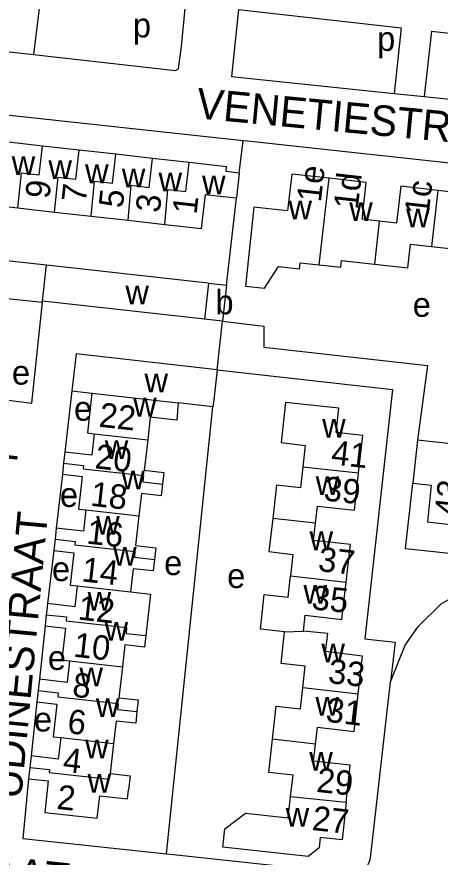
# Model space of a CAD drawing. Extents: x 161936 to 163647, y 386450 to 388633.
# Drawn here: x 162845.1 to 162914.6, y 388209.6 to 388347.4 of the extents above; entities that cross this region are included whole.
import ezdxf

# ---------------------------------------------------------------- set-up
doc = ezdxf.new("R2010")
doc.units = 0
for name, color, linetype in [('BLT_Basislijn', 7, 'Continuous'), ('BLT_Bebouwing', 7, 'Continuous'), ('BLT_Centroide', 7, 'Continuous'), ('BLT_Huisnummer', 7, 'Continuous'), ('BLT_Huisnummer_ tussenligend', 7, 'Continuous'), ('BLT_Onderverdeling_panden', 7, 'Continuous'), ('BLT_Straatnaam', 7, 'Continuous')]:
    doc.layers.add(name, color=color, linetype=linetype)

msp = doc.modelspace()

# ---------------------------------------------------------------- linework, layer by layer
at = {"layer": 'BLT_Basislijn'}
for p, q in [((162849.18, 388352.56), (162847.79, 388341.21)), ((162872.08, 388342.54), (162872.83, 388349.94)), ((162881.44, 388348.58), (162880.32, 388337.62)), ((162908.19, 388345.61), (162907, 388334.84)), ((162913.16, 388345.06), (162911.97, 388334.32)), ((162842.82, 388341.76), (162847.79, 388341.21)), ((162880.32, 388337.62), (162907, 388334.84)), ((162882.23, 388327.06), (162798.44, 388336.12)), ((162907, 388334.84), (162911.97, 388334.32)), ((162911.97, 388334.32), (162937.75, 388331.64)), ((162881.58, 388321.77), (162882.23, 388327.06)), ((162879.49, 388303.39), (162881.11, 388317.7)), ((162849.92, 388306.66), (162795.81, 388312.41)), ((162841.69, 388301.4), (162849.25, 388300.61)), ((162849.25, 388300.61), (162849.27, 388300.76)), ((162877.93, 388289.52), (162878.84, 388297.49)), ((162854.11, 388286.03), (162852.94, 388276.01)), ((162869.65, 388210.1), (162877.26, 388283.45)), ((162852.54, 388272.38), (162851.53, 388263.54)), ((162851.12, 388259.85), (162850.1, 388251.15)), ((162849.69, 388247.52), (162848.77, 388238.74)), ((162848.36, 388235.01), (162847.39, 388226.16)), ((162846.97, 388222.43), (162846.04, 388212.6)), ((162846.04, 388212.6), (162869.65, 388210.1))]:
    msp.add_line(p, q, dxfattribs=at)
for points in [[(162881.44, 388348.58), (162908.19, 388345.61)], [(162913.16, 388345.06), (162938.68, 388342.23), (162937.75, 388331.64)], [(162847.79, 388341.21), (162871.09, 388338.6), (162871.63, 388338.88), (162872.08, 388342.54)], [(162951.3, 388275.21), (162942.09, 388314.98), (162941.51, 388316.33), (162936.9, 388320.8), (162935.74, 388321.27), (162882.96, 388326.98), (162882.23, 388327.06)], [(162838.47, 388285.16), (162847.52, 388284.01), (162849.25, 388300.61)], [(162878.84, 388297.49), (162885.59, 388296.66), (162885.62, 388293.24)], [(162885.62, 388293.24), (162912.47, 388290.19), (162910.85, 388277.98)], [(162877.93, 388289.52), (162906.73, 388286.25), (162902.18, 388245.39), (162907.18, 388244.8), (162906.41, 388238.31)], [(162924.84, 388255.15), (162923.3, 388258.62), (162908.88, 388260.15), (162910.06, 388270.93)], [(162906.41, 388238.31), (162908.82, 388244.31), (162910.99, 388247.44), (162914.77, 388251.14), (162918.53, 388253.18), (162924.84, 388255.15)], [(162869.65, 388210.1), (162870.77, 388209.98), (162900.24, 388206.82), (162900.76, 388206.89), (162901.26, 388207.05), (162901.77, 388207.31), (162902.15, 388207.62), (162902.57, 388208.08), (162902.86, 388208.55), (162903.08, 388209.19), (162903.19, 388209.86), (162906.41, 388238.31)]]:
    msp.add_lwpolyline(points, dxfattribs=at)
at = {"layer": 'BLT_Bebouwing'}
for p, q in [((162849.27, 388326.19), (162843.26, 388326.87)), ((162855.29, 388325.52), (162849.27, 388326.19)), ((162861.3, 388324.85), (162855.29, 388325.52)), ((162867.32, 388324.17), (162861.3, 388324.85)), ((162873.34, 388323.5), (162867.32, 388324.17)), ((162881.58, 388321.77), (162881.11, 388317.7)), ((162839.16, 388316.73), (162845.2, 388316.05)), ((162845.2, 388316.05), (162851.24, 388315.37)), ((162851.24, 388315.37), (162857.28, 388314.7)), ((162857.28, 388314.7), (162863.32, 388314.02)), ((162863.32, 388314.02), (162869.36, 388313.34)), ((162876.51, 388303.72), (162879.49, 388303.39)), ((162879.49, 388303.39), (162878.84, 388297.49)), ((162875.86, 388297.82), (162849.27, 388300.76)), ((162878.84, 388297.49), (162875.86, 388297.82)), ((162854.11, 388286.03), (162857.38, 388285.67)), ((162877.26, 388283.45), (162871.57, 388284.08)), ((162910.85, 388277.98), (162910.06, 388270.93)), ((162852.94, 388276.01), (162852.74, 388274.2)), ((162852.74, 388274.2), (162852.54, 388272.38)), ((162852.54, 388272.38), (162855.79, 388272.02)), ((162851.53, 388263.54), (162851.33, 388261.7)), ((162851.33, 388261.7), (162851.12, 388259.85)), ((162851.12, 388259.85), (162854.42, 388259.49)), ((162849.69, 388247.52), (162853.03, 388247.14)), ((162848.77, 388238.74), (162848.57, 388236.88)), ((162848.57, 388236.88), (162848.36, 388235.01)), ((162848.36, 388235.01), (162851.63, 388234.65)), ((162847.39, 388226.16), (162847.18, 388224.29)), ((162847.18, 388224.29), (162846.97, 388222.43)), ((162846.97, 388222.43), (162850.23, 388222.07))]:
    msp.add_line(p, q, dxfattribs=at)
for points in [[(162881.58, 388321.77), (162879.41, 388322.01), (162879.5, 388322.81), (162873.34, 388323.5)], [(162896.36, 388320.93), (162890.21, 388321.61), (162889.49, 388315.57), (162886.45, 388315.89), (162883.97, 388316.16), (162882.59, 388303.24), (162885.72, 388302.89), (162888.01, 388306.45)], [(162904.58, 388313.88), (162901.75, 388314.2), (162902.44, 388320.24), (162896.36, 388320.93)], [(162914.21, 388318.92), (162908.1, 388319.61), (162907.41, 388313.55), (162904.58, 388313.88)], [(162869.36, 388313.34), (162875.39, 388312.67), (162876.02, 388318.27), (162878.95, 388317.94), (162881.11, 388317.7)], [(162922.47, 388311.84), (162919.63, 388312.16), (162920.32, 388318.22), (162914.21, 388318.92)], [(162903.77, 388306.81), (162909.26, 388306.2), (162909.68, 388310.13), (162913.17, 388309.75)], [(162913.17, 388309.75), (162916.65, 388309.37), (162916.23, 388305.41), (162921.65, 388304.78)], [(162888.01, 388306.45), (162891.46, 388306.06), (162891.58, 388307.06), (162894.69, 388306.72)], [(162894.69, 388306.72), (162898.26, 388306.32), (162898.37, 388307.41), (162903.77, 388306.81)], [(162849.27, 388300.76), (162849.82, 388305.73), (162849.92, 388306.66)], [(162876.51, 388303.72), (162874.53, 388303.94), (162849.92, 388306.66)], [(162877.93, 388289.52), (162854.79, 388292.11), (162854.11, 388286.03)], [(162877.93, 388289.52), (162877.38, 388284.55), (162877.26, 388283.45)], [(162857.38, 388285.67), (162856.67, 388279.14), (162857.78, 388279.01)], [(162871.57, 388284.08), (162871.31, 388281.22), (162866.96, 388281.71), (162866.55, 388278.03)], [(162901.17, 388272.58), (162901.86, 388278.73), (162897.51, 388279.21), (162897.95, 388283.19), (162889.2, 388284.15), (162888.45, 388277.55), (162892.4, 388277.09), (162892.02, 388273.61)], [(162857.78, 388279.01), (162857.39, 388275.51), (162852.94, 388276.01)], [(162866.55, 388278.03), (162865.99, 388273.04), (162869.19, 388272.68), (162868.98, 388270.76)], [(162919.6, 388272.99), (162916.09, 388273.37), (162916.54, 388277.32), (162915.82, 388277.43), (162910.85, 388277.98)], [(162892.02, 388273.61), (162891.62, 388270.12), (162887.67, 388270.56), (162887.07, 388265.12)], [(162894.09, 388264.32), (162894.41, 388267.15), (162900.48, 388266.49), (162901.17, 388272.58)], [(162855.79, 388272.02), (162855.19, 388266.64), (162856.41, 388266.51)], [(162868.98, 388270.76), (162868.76, 388268.85), (162865.52, 388269.21), (162865.11, 388265.54)], [(162910.06, 388270.93), (162913.09, 388270.6), (162912.47, 388264.54), (162918.61, 388263.86)], [(162856.41, 388266.51), (162856.02, 388263.04), (162851.53, 388263.54)], [(162865.11, 388265.54), (162864.57, 388260.67), (162867.88, 388260.3), (162867.66, 388258.4)], [(162887.07, 388265.12), (162886.46, 388259.67), (162890.4, 388259.18), (162890.01, 388255.7)], [(162899.15, 388254.67), (162899.86, 388260.85), (162893.77, 388261.49), (162894.09, 388264.32)], [(162854.42, 388259.49), (162853.83, 388254.18), (162854.99, 388254.05)], [(162867.66, 388258.4), (162867.45, 388256.5), (162864.16, 388256.87), (162863.74, 388253.08)], [(162889.02, 388246.54), (162885.05, 388246.98), (162885.38, 388250), (162885.67, 388252.66), (162889.62, 388252.21), (162890.01, 388255.7)], [(162892.14, 388246.65), (162892.4, 388249.23), (162898.44, 388248.54), (162898.61, 388250), (162899.15, 388254.67)], [(162854.99, 388254.05), (162854.61, 388250.64), (162850.1, 388251.15)], [(162863.74, 388253.08), (162866.99, 388252.71), (162866.23, 388245.9)], [(162850.1, 388251.15), (162849.97, 388250), (162849.9, 388249.33)], [(162849.9, 388249.33), (162849.69, 388247.52)], [(162853.03, 388247.14), (162852.44, 388241.91), (162853.72, 388241.77)], [(162892.02, 388237.39), (162892.41, 388240.9), (162888.44, 388241.34), (162889.02, 388246.54)], [(162901.12, 388236.37), (162901.8, 388242.53), (162895.75, 388243.29), (162896.1, 388246.24), (162892.14, 388246.65)], [(162866.23, 388245.9), (162866.02, 388244.01), (162862.79, 388244.37), (162862.39, 388240.8)], [(162853.72, 388241.77), (162853.32, 388238.23), (162848.77, 388238.74)], [(162862.39, 388240.8), (162861.82, 388235.71), (162865.01, 388235.35), (162864.79, 388233.44)], [(162887.05, 388228.93), (162887.65, 388234.32), (162891.62, 388233.88), (162892.02, 388237.39)], [(162894.09, 388228.09), (162894.42, 388230.9), (162900.43, 388230.18), (162901.12, 388236.37)], [(162851.63, 388234.65), (162851.03, 388229.3), (162852.26, 388229.16)], [(162864.79, 388233.44), (162864.58, 388231.53), (162861.36, 388231.89), (162860.95, 388228.19)], [(162852.26, 388229.16), (162851.87, 388225.66), (162847.39, 388226.16)], [(162890.01, 388219.48), (162890.41, 388223), (162886.43, 388223.44), (162887.05, 388228.93)], [(162860.95, 388228.19), (162860.4, 388223.28)], [(162899.13, 388218.5), (162899.79, 388224.63), (162893.76, 388225.29), (162894.09, 388228.09)], [(162860.4, 388223.28), (162863.65, 388222.92), (162863.39, 388220.6)], [(162850.23, 388222.07), (162849.65, 388216.91), (162858.27, 388215.94), (162858.68, 388219.64), (162863.22, 388219.13), (162863.39, 388220.6)], [(162899.13, 388218.5), (162898.47, 388212.38), (162894.89, 388212.77), (162894.71, 388211.08), (162892.89, 388209.66), (162878.89, 388211.2), (162879.23, 388214.23), (162882.6, 388216.79), (162889.62, 388216.01), (162890.01, 388219.48)]]:
    msp.add_lwpolyline(points, dxfattribs=at)
at = {"layer": 'BLT_Onderverdeling_panden'}
for p, q in [((162894.69, 388306.72), (162896.36, 388320.93)), ((162914.21, 388318.92), (162913.17, 388309.75)), ((162904.58, 388313.88), (162903.77, 388306.81)), ((162876.51, 388303.72), (162875.86, 388297.82)), ((162857.38, 388285.67), (162871.57, 388284.08)), ((162857.78, 388279.01), (162866.55, 388278.03)), ((162892.02, 388273.61), (162901.17, 388272.58)), ((162856.41, 388266.51), (162865.11, 388265.54)), ((162894.09, 388264.32), (162887.07, 388265.12)), ((162890.01, 388255.7), (162899.15, 388254.67)), ((162854.99, 388254.05), (162863.74, 388253.08)), ((162889.02, 388246.54), (162892.14, 388246.65)), ((162853.72, 388241.77), (162862.39, 388240.8)), ((162892.02, 388237.39), (162901.12, 388236.37)), ((162852.26, 388229.16), (162860.95, 388228.19)), ((162894.09, 388228.09), (162887.05, 388228.93)), ((162899.13, 388218.5), (162890.01, 388219.48))]:
    msp.add_line(p, q, dxfattribs=at)
for points in [[(162845.2, 388316.05), (162845.8, 388321.79), (162848.74, 388321.46), (162849.27, 388326.19)], [(162851.24, 388315.37), (162851.82, 388321.11), (162854.76, 388320.78), (162855.29, 388325.52)], [(162857.28, 388314.7), (162857.83, 388320.44), (162860.77, 388320.11), (162861.3, 388324.85)], [(162863.32, 388314.02), (162863.85, 388319.76), (162866.79, 388319.43), (162867.32, 388324.17)], [(162869.36, 388313.34), (162869.87, 388319.09), (162872.81, 388318.76), (162873.34, 388323.5)], [(162852.74, 388274.2), (162856.01, 388273.83), (162855.93, 388273.23), (162865.88, 388272.18), (162865.75, 388271.12), (162868.98, 388270.76)], [(162851.33, 388261.7), (162854.62, 388261.32), (162854.57, 388260.78), (162864.46, 388259.67), (162864.36, 388258.77), (162867.66, 388258.4)], [(162849.9, 388249.33), (162853.23, 388248.96), (162853.16, 388248.33), (162863.09, 388247.22), (162862.99, 388246.26), (162866.23, 388245.9)], [(162848.57, 388236.88), (162851.83, 388236.51), (162851.77, 388235.88), (162861.71, 388234.77), (162861.59, 388233.8), (162864.79, 388233.44)], [(162847.18, 388224.29), (162850.43, 388223.93), (162850.38, 388223.43), (162860.3, 388222.33), (162860.4, 388223.28)]]:
    msp.add_lwpolyline(points, dxfattribs=at)

# ---------------------------------------------------------------- texts
at = {"layer": 'BLT_Centroide'}
for s, p in [('p', (162864.12, 388344.03)), ('p', (162904.22, 388341.81)), ('w', (162844.22, 388321.45)), ('w', (162850.25, 388320.78)), ('w', (162856.27, 388320.11)), ('w', (162862.3, 388319.42)), ('w', (162868.33, 388318.77)), ('w', (162875.47, 388318.3)), ('w', (162889.66, 388314.16)), ('w', (162899.64, 388313.92)), ('w', (162908.98, 388312.86)), ('w', (162862.89, 388300.25)), ('b', (162877.67, 388298.61)), ('e', (162910.07, 388298.19)), ('e', (162844.26, 388287.07)), ('w', (162866.02, 388285.78)), ('w', (162864.16, 388281.84)), ('e', (162854.45, 388281.15)), ('w', (162895.19, 388278.38)), ('w', (162859.5, 388274.88)), ('w', (162862.21, 388269.88)), ('w', (162894.13, 388268.97)), ('e', (162852.14, 388267.01)), ('w', (162858.09, 388262.47)), ('w', (162893.12, 388259.91)), ('w', (162860.87, 388257.38)), ('e', (162869.24, 388255.83)), ('e', (162850.83, 388254.84)), ('e', (162879.6, 388253.71)), ('w', (162892.12, 388251.12)), ('w', (162856.68, 388249.97)), ('w', (162859.47, 388245.06)), ('w', (162895.07, 388241.5)), ('e', (162850.16, 388240.27)), ('w', (162855.34, 388237.59)), ('w', (162858.04, 388232.53)), ('w', (162894.09, 388232.75)), ('e', (162847.87, 388230.17)), ('w', (162856.27, 388225.75)), ('w', (162893.08, 388223.72)), ('w', (162856.67, 388220.12)), ('w', (162889.2, 388214.56))]:
    msp.add_text(s, height=4, dxfattribs=at).set_placement(p)
at = {"layer": 'BLT_Huisnummer'}
for s, rotation, p in [('1e', 83.508, (162894.98, 388316.89)), ('9', 83.6087, (162850.4, 388317.45)), ('1c', 83.4845, (162912.68, 388314.73)), ('5', 83.6081, (162862.45, 388315.93)), ('1', 83.6149, (162874.56, 388314.89)), ('22', 353.6307, (162858.43, 388280.18)), ('41', 353.7428, (162896.56, 388274.01)), ('18', 353.6312, (162857.04, 388267.21)), ('43', 83.8513, (162917.59, 388265.3)), ('14', 353.6297, (162855.58, 388254.81)), ('35', 354.1792, (162893.35, 388250.22)), ('10', 353.6287, (162854.25, 388242.46)), ('31', 353.2592, (162895.67, 388231.8)), ('6', 353.633, (162853.24, 388229.91)), ('2', 353.6299, (162851.5, 388217.49)), ('27', 353.7294, (162893.42, 388214.02))]:
    msp.add_text(s, height=4, rotation=rotation, dxfattribs=at).set_placement(p)
at = {"layer": 'BLT_Huisnummer_ tussenligend'}
for s, rotation, p in [('1d', 83.5135, (162901.04, 388315.7)), ('7', 83.6081, (162856.36, 388316.83)), ('3', 83.6149, (162868.52, 388315.15)), ('20', 353.6312, (162857.76, 388273.35)), ('39', 353.938, (162895.34, 388268.08)), ('16', 353.6297, (162856.39, 388261.02)), ('37', 353.5669, (162894.41, 388256.51)), ('12', 353.6287, (162854.98, 388248.56)), ('33', 353.6177, (162896.04, 388238.14)), ('8', 353.633, (162854.06, 388235.91)), ('4', 353.6299, (162852.5, 388223.59)), ('29', 353.8634, (162894.14, 388220.28))]:
    msp.add_text(s, height=4, rotation=rotation, dxfattribs=at).set_placement(p)
at = {"layer": 'BLT_Straatnaam'}
for s, rotation, p in [('VENETIESTRAAT', 354.6207, (162874.37, 388330.77)), ('UDINESTRAAT', 353.516, (162797.91, 388275.66)), ('UDINESTRAAT', 84.6373, (162845.77, 388218.99)), ('TARANTOSTRAAT', 353.8977, (162795.37, 388209.75))]:
    msp.add_text(s, height=5, rotation=rotation, dxfattribs=at).set_placement(p)

doc.saveas('drawing.dxf')
